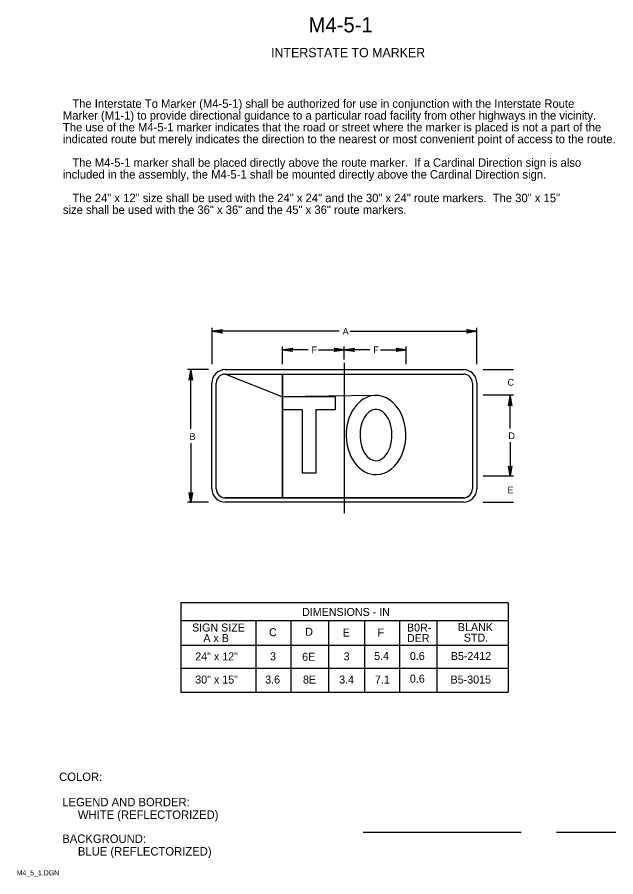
# Model space of a CAD drawing. Extents: x 0.013 to 0.191, y 0.004 to 0.259.
import ezdxf

# ---------------------------------------------------------------- set-up
doc = ezdxf.new("R2010")
doc.units = 0
for name, color, linetype in [('1', 7, 'Continuous'), ('2', 7, 'Continuous'), ('3', 7, 'Continuous')]:
    doc.layers.add(name, color=color, linetype=linetype)

# ---------------------------------------------------------------- blocks, each defined once
blk = doc.blocks.new('RARROW')
at = {"layer": '3'}
for p, q in [((-2.156, 0.285), (-2.2665, 0.384625)), ((-2.2665, 0.384625), (0, 0)), ((0, 0), (-2.2665, -0.379125)), ((-2.156, 0.285), (-2.075625, 0.12075)), ((0, 0), (-2.156, 0.285)), ((-2.14975, -0.2705), (0, 0)), ((-2.075625, 0.12075), (0, 0)), ((0, 0), (-2.074, -0.108)), ((-2.2665, -0.379125), (-2.14975, -0.2705)), ((-2.074, -0.108), (-2.14975, -0.2705))]:
    blk.add_line(p, q, dxfattribs=at)

msp = doc.modelspace()

# ---------------------------------------------------------------- linework, layer by layer
at = {"layer": '1'}
for p, q in [((0.11544, 0.01723), (0.16242, 0.01723)), ((0.17295, 0.01723), (0.19056, 0.01723))]:
    msp.add_line(p, q, dxfattribs=at)
at = {"layer": '3'}
for p, q in [((0.07063, 0.15611), (0.07063, 0.16687)), ((0.10837, 0.16587), (0.07063, 0.16587)), ((0.11163, 0.16587), (0.14925, 0.16587)), ((0.14925, 0.15611), (0.14925, 0.16687)), ((0.0915, 0.15611), (0.0915, 0.16137)), ((0.10988, 0.1575), (0.10988, 0.16137)), ((0.12825, 0.15611), (0.12825, 0.16137)), ((0.09913, 0.16037), (0.0915, 0.16037)), ((0.10225, 0.16037), (0.10988, 0.16037)), ((0.1175, 0.16037), (0.10988, 0.16037)), ((0.12062, 0.16037), (0.12825, 0.16037)), ((0.10988, 0.1565), (0.10988, 0.11188)), ((0.06954, 0.1545), (0.06329, 0.1545)), ((0.06429, 0.1369), (0.06429, 0.1545)), ((0.0745, 0.1545), (0.14525, 0.1545)), ((0.0745, 0.1532), (0.14525, 0.1532)), ((0.0745, 0.1532), (0.14525, 0.1532)), ((0.0915, 0.15325), (0.0915, 0.11638)), ((0.0915, 0.11638), (0.0915, 0.15325)), ((0.15113, 0.1545), (0.16012, 0.1545)), ((0.0705, 0.11913), (0.0705, 0.1505)), ((0.0718, 0.11913), (0.0718, 0.1505)), ((0.14795, 0.1505), (0.14795, 0.11913)), ((0.14925, 0.1505), (0.14925, 0.11913)), ((0.10725, 0.14638), (0.0915, 0.14638)), ((0.10725, 0.14263), (0.10725, 0.14638)), ((0.15113, 0.147), (0.16012, 0.147)), ((0.15913, 0.143), (0.15913, 0.147)), ((0.15913, 0.137), (0.15913, 0.147)), ((0.0915, 0.14263), (0.09738, 0.14263)), ((0.09738, 0.14263), (0.09738, 0.12387)), ((0.1015, 0.12387), (0.1015, 0.14263)), ((0.1015, 0.14263), (0.10725, 0.14263)), ((0.15913, 0.133), (0.15913, 0.123)), ((0.06429, 0.13263), (0.06429, 0.11512)), ((0.09738, 0.12387), (0.1015, 0.12387)), ((0.15113, 0.123), (0.16012, 0.123)), ((0.06954, 0.11512), (0.06329, 0.11512)), ((0.0745, 0.11643), (0.14525, 0.11643)), ((0.14525, 0.11643), (0.0745, 0.11643)), ((0.14525, 0.11513), (0.0745, 0.11513)), ((0.15113, 0.11513), (0.16012, 0.11513)), ((0.06125, 0.08538), (0.1585, 0.08538)), ((0.06129, 0.08537), (0.06129, 0.0588)), ((0.15854, 0.08537), (0.15854, 0.0588)), ((0.15854, 0.07994), (0.06129, 0.07994)), ((0.08354, 0.07994), (0.08354, 0.0588)), ((0.09403, 0.07994), (0.09403, 0.0588)), ((0.10515, 0.07994), (0.10515, 0.0588)), ((0.11592, 0.07994), (0.11592, 0.0588)), ((0.12629, 0.07994), (0.12629, 0.0588)), ((0.13735, 0.07994), (0.13735, 0.0588)), ((0.06129, 0.07271), (0.15854, 0.07271)), ((0.06129, 0.0659), (0.15854, 0.0659)), ((0.06129, 0.0588), (0.15854, 0.0588))]:
    msp.add_line(p, q, dxfattribs=at)
msp.add_lwpolyline([(0.11892, 0.14682), (0.09146, 0.14643), (0.0745, 0.1532)], dxfattribs=at)
for centre, radius, start, end in [((0.0745, 0.1505), 0.004, 90, 180), ((0.0745, 0.1505), 0.0027, 90, 180), ((0.14525, 0.1505), 0.004, 0, 90), ((0.14525, 0.1505), 0.0027, 0, 90), ((0.0745, 0.11913), 0.004, 180, 270), ((0.0745, 0.11913), 0.0027, 180, 270), ((0.14525, 0.11913), 0.004, 270, 0), ((0.14525, 0.11913), 0.0027, 270, 0)]:
    msp.add_arc(centre, radius, start, end, dxfattribs=at)
for major_axis, ratio, start_param, end_param in [((0, -0.01175), 0.755319, 3.182942, 6.296845), ((0, -0.01175), 0.755319, 0.013648, 3.183761), ((0, -0.00762), 0.622951, 3.215547, 6.284119), ((0, -0.00762), 0.622951, 0.000933, 3.21373)]:
    msp.add_ellipse((0.11929, 0.13508), major_axis=major_axis, ratio=ratio, start_param=start_param, end_param=end_param, dxfattribs=at)

# ---------------------------------------------------------------- block references
at = {"layer": '3', "xscale": 0.0013236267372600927, "yscale": 0.001309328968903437}
for p, rotation in [((0.07063, 0.16587), 180), ((0.0915, 0.16037), 180), ((0.10988, 0.16037), 180), ((0.06425, 0.15438), 90), ((0.15913, 0.14675), 90), ((0.15913, 0.14675), 90), ((0.15913, 0.12287), -90), ((0.06425, 0.115), -90)]:
    msp.add_blockref('RARROW', p, dxfattribs=dict(at, rotation=rotation))
for p in [(0.14925, 0.16587), (0.10988, 0.16037), (0.12825, 0.16037)]:
    msp.add_blockref('RARROW', p, dxfattribs=at)

# ---------------------------------------------------------------- texts
at = {"layer": '1'}
for s, height, p in [('M4-5-1', 0.0045, (0.09925, 0.25462)), ('INTERSTATE TO MARKER', 0.0027503, (0.08812, 0.24725)), ('COLOR:', 0.0025, (0.02513, 0.03238)), (' LEGEND AND BORDER:', 0.0024998, (0.02513, 0.02488)), ('      WHITE (REFLECTORIZED)', 0.0024998, (0.02513, 0.02113)), (' BACKGROUND:', 0.0024998, (0.02513, 0.014)), ('      BLUE (REFLECTORIZED)', 0.0024998, (0.02513, 0.01025)), ('M4_5_1.DGN', 0.0015, (0.0125, 0.00438))]:
    msp.add_text(s, height=height, dxfattribs=at).set_placement(p)
at = {"layer": '2'}
for s, height, p in [('   The Interstate To Marker (M4-5-1) shall be authorized for use in conjunction with the Interstate Route ', 0.00249975, (0.02625, 0.23222)), ('Marker (M1-1) to provide directional guidance to a particular road facility from other highways in the vicinity.  ', 0.00249975, (0.02625, 0.22872)), ('The use of the M4-5-1 marker indicates that the road or street where the marker is placed is not a part of the ', 0.00249975, (0.02625, 0.22522)), ('indicated route but merely indicates the direction to the nearest or most convenient point of access to the route.', 0.00249975, (0.02625, 0.22172)), ('   The M4-5-1 marker shall be placed directly above the route marker.  If a Cardinal Direction sign is also', 0.00249975, (0.02625, 0.21472)), ('included in the assembly, the M4-5-1 shall be mounted directly above the Cardinal Direction sign.', 0.0024998, (0.02625, 0.21122)), ('   The 24" x 12" size shall be used with the 24" x 24" and the 30" x 24" route markers.  The 30" x 15"', 0.00249975, (0.02625, 0.20422)), ('size shall be used with the 36" x 36" and the 45" x 36" route markers.', 0.0024998, (0.02625, 0.20072))]:
    msp.add_text(s, height=height, dxfattribs=at).set_placement(p)
at = {"layer": '3'}
for s, height, p in [('A', 0.002, (0.10938, 0.16487)), ('F', 0.002, (0.10013, 0.15938)), ('F', 0.002, (0.1185, 0.15938)), ('C', 0.002, (0.15838, 0.14975)), ('B', 0.002, (0.06388, 0.13362)), ('D', 0.002, (0.15863, 0.13387)), ('E', 0.002, (0.15838, 0.11775)), ('DIMENSIONS - IN', 0.0023752, (0.09732, 0.08138)), ('SIGN SIZE', 0.002375, (0.06463, 0.07675)), ('B0R-', 0.002375, (0.1285, 0.07675)), ('BLANK', 0.002375, (0.14363, 0.07687)), ('C', 0.00238, (0.0875, 0.07537)), ('D', 0.00238, (0.09825, 0.0755)), ('E', 0.00238, (0.10938, 0.07525)), ('F', 0.00238, (0.11975, 0.07525)), ('A x B', 0.002375, (0.068, 0.07362)), ('DER', 0.002375, (0.1285, 0.07362)), ('STD.', 0.002375, (0.14538, 0.07375)), ('24" x 12"', 0.002375, (0.06559, 0.06819)), ('3', 0.00238, (0.08781, 0.06819)), ('6E', 0.002375, (0.09735, 0.06806)), ('3', 0.00238, (0.10968, 0.06819)), ('5.4', 0.002375, (0.11873, 0.06831)), ('0.6', 0.002375, (0.12937, 0.06831)), ('B5-2412', 0.002375, (0.14152, 0.06831)), ('0.6', 0.002375, (0.12937, 0.06156)), ('30" x 15"', 0.002375, (0.06559, 0.06131)), ('3.6', 0.002375, (0.08637, 0.06131)), ('8E', 0.002375, (0.0976, 0.06131)), ('3.4', 0.002375, (0.10836, 0.06131)), ('7.1', 0.002375, (0.11899, 0.06131)), ('B5-3015', 0.002375, (0.14147, 0.06131))]:
    msp.add_text(s, height=height, dxfattribs=at).set_placement(p)

doc.saveas('drawing.dxf')
